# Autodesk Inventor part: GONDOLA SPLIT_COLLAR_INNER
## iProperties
Shininess: 64.0
Length Units: 11272
Angle Units: 11279
Time Units: 11290
Mass Units: 11286
Length Display Precision: 3
Angle Display Precision: 2
Compacted: True
Part Number: GONDOLA SPLIT_COLLAR_INNER
Document SubType Name: Modeling
Created: 2004-08
Designer: John Blackburn
Manufacturer: Standard
Standards Organization: Custom
Material: Delrin, Black
Density: 0.0
Volumn: 0.0
Area: 0.0
PropertySet Name: Model Information
Control State: 0
Master: False
Checked Out: False
Author: John Blackburn
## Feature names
1. Base1
2. ExtrusionThru1
